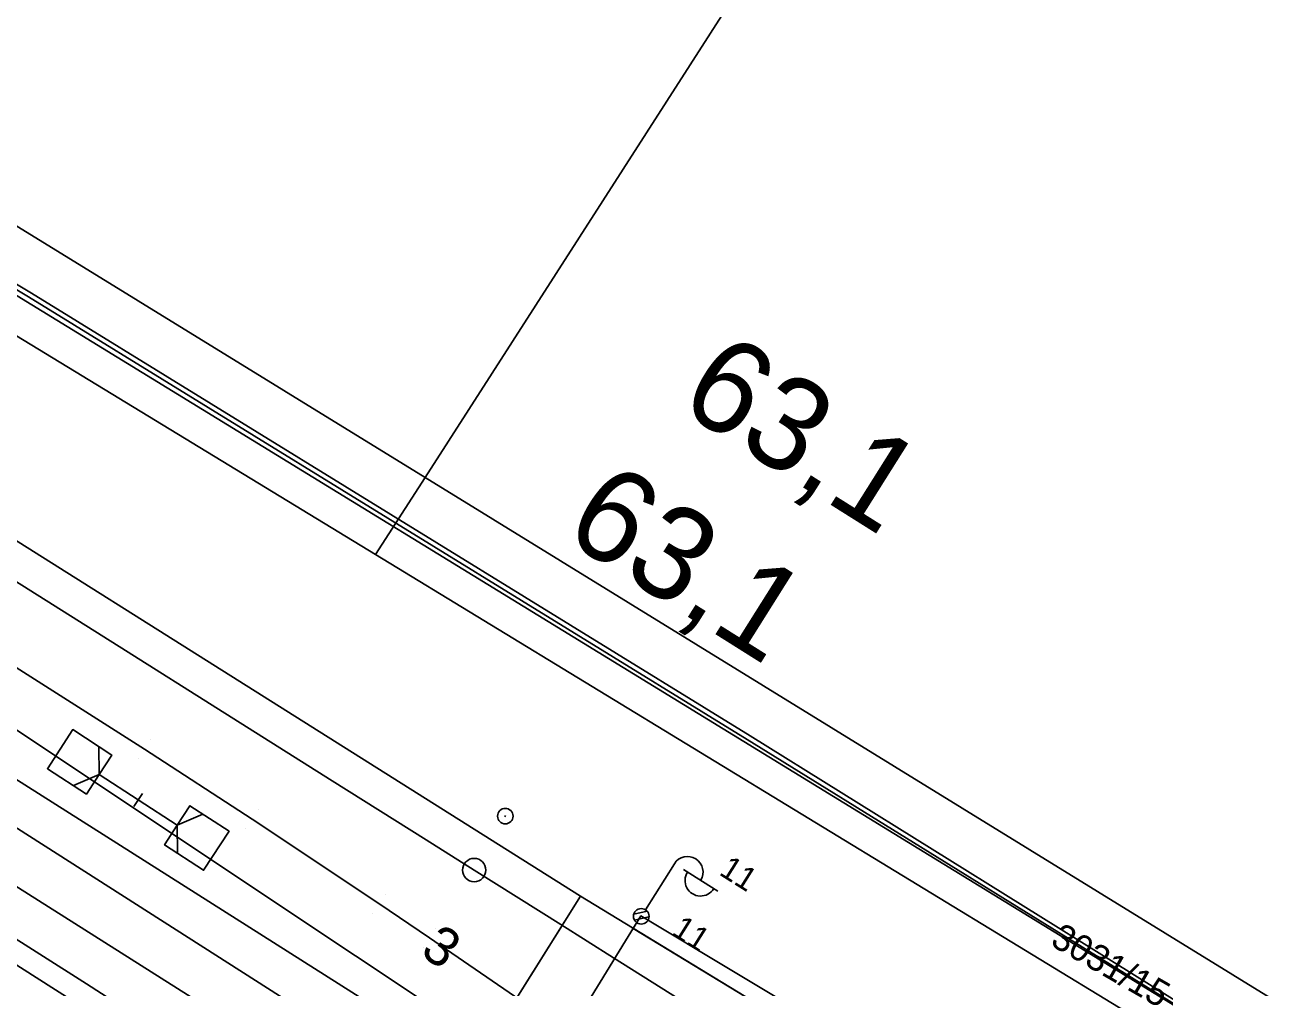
# Model space of a CAD drawing. Extents: x -621168 to -620292, y -1122748 to -1122069.
# Drawn here: x -620574.7 to -620493.7, y -1122527.1 to -1122465.1 of the extents above; entities that cross this region are included whole.
import ezdxf

# ---------------------------------------------------------------- set-up
doc = ezdxf.new("R2010")
doc.units = 0
for name, color, linetype in [('060601_EOV', 7, 'Continuous'), ('060604_ROZVODY_SEE', 7, 'Continuous'), ('CETIN', 7, 'Continuous'), ('HranDP', 7, 'Continuous'), ('Hranice parcel', 7, 'Continuous'), ('Parcelní čísla', 7, 'Continuous'), ('PS 06-14-01_trasa_sdělovací_nové', 7, 'Continuous'), ('SEE', 7, 'Continuous'), ('SSZT', 7, 'Continuous'), ('SSZT-DK', 7, 'Continuous'), ('UZEMNĚNÍ', 7, 'Continuous'), ('Vnitřní kresba', 7, 'Continuous'), ('Vrstva 1', 7, 'Continuous'), ('Vrstva 25', 7, 'Continuous'), ('Vrstva 62', 7, 'Continuous'), ('Vrstva 7', 7, 'Continuous'), ('ČD-T', 7, 'Continuous')]:
    doc.layers.add(name, color=color, linetype=linetype)

msp = doc.modelspace()

# ---------------------------------------------------------------- linework, layer by layer
at = {"layer": '060601_EOV'}
msp.add_lwpolyline([(-620377.179, -1122637.257), (-620411.557, -1122614.916), (-620424.156, -1122607.087), (-620443.525, -1122595.005), (-620456.111, -1122587.123), (-620447.823, -1122572.959), (-620450.948, -1122571.455), (-620470.592, -1122561.479), (-620499.61, -1122545.574), (-620522.038, -1122531.471), (-620538.89, -1122521.208), (-620599.215, -1122483.216), (-620683.524, -1122429.444), (-620729.121, -1122400.659), (-620738.886, -1122415.694), (-620750.529, -1122408.246), (-620763.558, -1122399.82), (-620784.65, -1122386.386), (-620822.218, -1122362.419), (-620817.53, -1122355.085), (-620826.407, -1122348.082), (-620839.916, -1122337.943), (-620848.842, -1122331.997), (-620848.834, -1122331.986)], dxfattribs=at)
at = {"layer": '060604_ROZVODY_SEE'}
msp.add_line((-620535.001, -1122522.477), (-620535.489, -1122523.279), dxfattribs=at)
msp.add_lwpolyline([(-620443.525, -1122595.005), (-620456.111, -1122587.123), (-620447.823, -1122572.959), (-620450.948, -1122571.455), (-620470.592, -1122561.479), (-620499.61, -1122545.574), (-620522.038, -1122531.471), (-620538.89, -1122521.208), (-620599.215, -1122483.216), (-620683.524, -1122429.444), (-620729.121, -1122400.659), (-620738.886, -1122415.694), (-620750.529, -1122408.246), (-620763.558, -1122399.82), (-620784.65, -1122386.386), (-620822.218, -1122362.419), (-620817.53, -1122355.085), (-620826.407, -1122348.082), (-620839.916, -1122337.943), (-620854.567, -1122328.184), (-620868.06, -1122319.694), (-620885.37, -1122308.815), (-620912.868, -1122291.527), (-620913.325, -1122292.255)], dxfattribs=at)
at = {"layer": 'CETIN'}
msp.add_lwpolyline([(-621086.886, -1122186.715), (-621044.703, -1122204.841), (-620975.938, -1122239.692), (-620943.103, -1122258.616), (-620748.436, -1122376.269), (-620484.52, -1122538.147)], dxfattribs=at)
at = {"layer": 'HranDP'}
msp.add_line((-620445.8, -1122563.95), (-620552.09, -1122499.2), dxfattribs=at)
for points in [[(-620847.72, -1122320.67), (-620838.83, -1122326.12), (-620768.63, -1122369.09), (-620748.53, -1122378.52), (-620702.13, -1122406.7), (-620691.02, -1122413.66), (-620638.48, -1122446.57), (-620552.09, -1122499.2)], [(-620821.12, -1122358.76), (-620741.46, -1122408.09), (-620679.51, -1122447.56), (-620545.92, -1122532.26), (-620521.41, -1122548.27), (-620511.29, -1122557.64)]]:
    msp.add_lwpolyline(points, dxfattribs=at)
at = {"layer": 'Hranice parcel'}
for p, q in [((-620548.9, -1122494.24), (-620477.85, -1122383.559)), ((-620688.16, -1122408.5), (-620548.9, -1122494.24)), ((-620552.09, -1122499.2), (-620548.9, -1122494.24)), ((-620548.9, -1122494.24), (-620475.79, -1122539.24)), ((-620445.8, -1122563.95), (-620552.09, -1122499.2))]:
    msp.add_line(p, q, dxfattribs=at)
for points in [[(-620847.72, -1122320.67), (-620838.83, -1122326.12), (-620768.63, -1122369.09), (-620748.53, -1122378.52), (-620702.13, -1122406.7), (-620691.02, -1122413.66), (-620638.48, -1122446.57), (-620552.09, -1122499.2)], [(-620821.12, -1122358.76), (-620741.46, -1122408.09), (-620679.51, -1122447.56), (-620545.92, -1122532.26), (-620521.41, -1122548.27), (-620511.29, -1122557.64)], [(-620821.12, -1122358.76), (-620807.67, -1122367.84), (-620645.72, -1122471.03), (-620587.17, -1122509.18), (-620511.29, -1122557.64)], [(-620557.45, -1122536.96), (-620684.91, -1122455.63), (-620825.92, -1122365.89)]]:
    msp.add_lwpolyline(points, dxfattribs=at)
at = {"layer": 'PS 06-14-01_trasa_sdělovací_nové'}
for points in [[(-620538.89, -1122521.208), (-620538.89, -1122521.208), (-620599.215, -1122483.216), (-620683.524, -1122429.444), (-620756.33, -1122383.523), (-620761.979, -1122392.397), (-620753.366, -1122398.538), (-620735.257, -1122410.106), (-620735.257, -1122410.106)], [(-620377.179, -1122637.257), (-620411.557, -1122614.916), (-620456.111, -1122587.123), (-620544.953, -1122530.859), (-620538.89, -1122521.208), (-620538.89, -1122521.208)]]:
    msp.add_lwpolyline(points, dxfattribs=at)
at = {"layer": 'SEE'}
msp.add_lwpolyline([(-620377.188, -1122637.273), (-620390.254, -1122629.02), (-620411.934, -1122614.961), (-620423.125, -1122608.012), (-620468.337, -1122579.91), (-620468.337, -1122579.91), (-620460.94, -1122568.103), (-620517.418, -1122533.032), (-620535.001, -1122522.477), (-620545.407, -1122539.454), (-620611.375, -1122497.696), (-620665.569, -1122462.755), (-620686.035, -1122449.829), (-620727.537, -1122423.183), (-620794.508, -1122379.862), (-620815.52, -1122356.954), (-620832.168, -1122344.663), (-620847.808, -1122332.592), (-620908.257, -1122294.686)], dxfattribs=at)
at = {"layer": 'SSZT'}
msp.add_lwpolyline([(-620879.238, -1122313.316), (-620842.993, -1122336.61), (-620835.049, -1122343.251), (-620812.66, -1122358.949), (-620764.902, -1122389.752), (-620688.594, -1122438.969), (-620596.981, -1122496.725), (-620576.744, -1122509.484), (-620506.746, -1122556.123), (-620447.293, -1122593.619), (-620377.761, -1122638.259)], dxfattribs=at)
at = {"layer": 'SSZT-DK'}
msp.add_lwpolyline([(-621084.334, -1122182.327), (-621080.248, -1122184.036), (-621051.504, -1122198.928), (-620999.37, -1122227.003), (-620959.935, -1122250.539), (-620931.349, -1122267.519), (-620900.269, -1122286.467), (-620889.147, -1122293.455), (-620783.743, -1122358.818), (-620712.751, -1122398.176), (-620653.117, -1122435.232), (-620617.363, -1122456.738), (-620574.425, -1122482.604), (-620528.157, -1122511.106), (-620496.311, -1122530.834), (-620515.025, -1122558.813), (-620500.383, -1122568.606), (-620465.393, -1122591.454), (-620452.16, -1122605.021), (-620438.234, -1122615.496), (-620392.309, -1122655.212), (-620389.253, -1122658.022)], dxfattribs=at)
at = {"layer": 'UZEMNĚNÍ'}
msp.add_lwpolyline([(-620535.001, -1122522.477), (-620535.489, -1122523.279), (-620522.038, -1122531.471), (-620499.61, -1122545.574), (-620487.514, -1122552.204), (-620470.592, -1122561.479), (-620459.297, -1122567.215), (-620458.667, -1122565.975)], dxfattribs=at)
at = {"layer": 'Vnitřní kresba'}
for p, q in [((-620570.69, -1122526.84), (-620613.12, -1122500)), ((-620504.94, -1122569.2), (-620570.69, -1122526.84))]:
    msp.add_line(p, q, dxfattribs=at)
at = {"layer": 'Vrstva 1'}
msp.add_line((-620544.953, -1122530.859), (-620538.89, -1122521.208), dxfattribs=at)
for points in [[(-620538.89, -1122521.208), (-620599.215, -1122483.216), (-620683.524, -1122429.444), (-620747.38, -1122389.133), (-620756.33, -1122383.523)], [(-620575.439, -1122500.82), (-620568.605, -1122505.122), (-620561.797, -1122509.415), (-620554.878, -1122513.77), (-620548.817, -1122517.58), (-620545.736, -1122519.521), (-620540.158, -1122523.031), (-620536.763, -1122525.164), (-620530.044, -1122529.401), (-620522.74, -1122533.999), (-620516.175, -1122538.134), (-620510.877, -1122541.462), (-620509.772, -1122542.153), (-620508.122, -1122543.191), (-620500.939, -1122547.694), (-620490.94, -1122553.975)], [(-620575.439, -1122500.82), (-620568.605, -1122505.122), (-620561.797, -1122509.415), (-620554.878, -1122513.77), (-620548.817, -1122517.58), (-620545.736, -1122519.521), (-620540.158, -1122523.031), (-620536.763, -1122525.164), (-620530.044, -1122529.401), (-620522.74, -1122533.999), (-620516.175, -1122538.134), (-620510.877, -1122541.462), (-620509.772, -1122542.153), (-620508.122, -1122543.191), (-620500.939, -1122547.694), (-620490.94, -1122553.975)], [(-620582.331, -1122501.971), (-620566.971, -1122511.728), (-620560.029, -1122516.238), (-620551.869, -1122521.685), (-620548.619, -1122523.887), (-620542.396, -1122528.151), (-620538.064, -1122531.158), (-620531.122, -1122535.952), (-620524.966, -1122540.177), (-620518.618, -1122544.427), (-620513.645, -1122547.697), (-620506.55, -1122552.247), (-620496.304, -1122558.659), (-620480.231, -1122568.734), (-620462.233, -1122580.043), (-620447.551, -1122589.267), (-620431.6, -1122599.485), (-620414.27, -1122610.379), (-620398.172, -1122620.479), (-620378.269, -1122633.015), (-620375.666, -1122634.655)]]:
    msp.add_lwpolyline(points, dxfattribs=at)
at = {"layer": 'Vrstva 25'}
for p, q in [((-620534.711, -1122522.078), (-620532.844, -1122519.118)), ((-620534.711, -1122522.078), (-620532.844, -1122519.118)), ((-620532.252, -1122519.491), (-620530.053, -1122520.878)), ((-620532.252, -1122519.491), (-620530.053, -1122520.878)), ((-620535.46, -1122522.37), (-620534.602, -1122522.175)), ((-620535.46, -1122522.37), (-620534.602, -1122522.175)), ((-620535.413, -1122522.743), (-620534.479, -1122522.532)), ((-620535.413, -1122522.743), (-620534.479, -1122522.532))]:
    msp.add_line(p, q, dxfattribs=at)
msp.add_circle((-620534.978, -1122522.501), 0.5, dxfattribs=at)
msp.add_circle((-620534.978, -1122522.501), 0.5, dxfattribs=at)
for centre, start, end in [((-620531.999, -1122519.651), 327.76448, 147.76448), ((-620531.999, -1122519.651), 327.76448, 147.76448), ((-620531.159, -1122520.195), 147.0619, 328.46705), ((-620531.159, -1122520.195), 147.0619, 328.46705)]:
    msp.add_arc(centre, 1, start, end, dxfattribs=at)
at = {"layer": 'Vrstva 62'}
for p, q in [((-620566.596, -1122511.103), (-620566.596, -1122511.103)), ((-620567.346, -1122512.352), (-620567.346, -1122512.352)), ((-620559.628, -1122515.637), (-620559.628, -1122515.637)), ((-620560.43, -1122516.839), (-620560.43, -1122516.839)), ((-620551.476, -1122521.073), (-620551.476, -1122521.073)), ((-620552.263, -1122522.298), (-620552.263, -1122522.298)), ((-620548.218, -1122523.275), (-620548.218, -1122523.275)), ((-620549.02, -1122524.499), (-620549.02, -1122524.499))]:
    msp.add_line(p, q, dxfattribs=at)
at = {"layer": 'Vrstva 7'}
for p, q in [((-620569.888, -1122513.372), (-620567.372, -1122515.006)), ((-620567.644, -1122515.425), (-620567.1, -1122514.587)), ((-620567.1, -1122514.587), (-620567.644, -1122515.425)), ((-620564.856, -1122516.64), (-620567.372, -1122515.006)), ((-620543.775, -1122516.023), (-620543.691, -1122516.077)), ((-620543.775, -1122516.023), (-620543.691, -1122516.077))]:
    msp.add_line(p, q, dxfattribs=at)
for points in [[(-620569.888, -1122513.372), (-620569.071, -1122512.114), (-620571.586, -1122510.479), (-620573.221, -1122512.995), (-620570.705, -1122514.629), (-620569.888, -1122513.372)], [(-620571.545, -1122514.084), (-620569.888, -1122513.372), (-620569.911, -1122511.568)], [(-620564.856, -1122516.64), (-620565.673, -1122517.898), (-620563.158, -1122519.533), (-620561.523, -1122517.017), (-620564.039, -1122515.383), (-620564.856, -1122516.64)], [(-620563.199, -1122515.928), (-620564.856, -1122516.64), (-620564.833, -1122518.444)]]:
    msp.add_lwpolyline(points, dxfattribs=at)
for centre, radius in [((-620543.733, -1122516.05), 0.5), ((-620543.733, -1122516.05), 0.5), ((-620545.736, -1122519.521), 0.75), ((-620545.736, -1122519.521), 0.75)]:
    msp.add_circle(centre, radius, dxfattribs=at)
at = {"layer": 'ČD-T'}
msp.add_lwpolyline([(-621084.188, -1122182.075), (-621080.06, -1122183.802), (-621051.317, -1122198.693), (-620999.183, -1122226.768), (-620959.747, -1122250.305), (-620931.162, -1122267.284), (-620900.082, -1122286.233), (-620888.96, -1122293.22), (-620783.556, -1122358.583), (-620712.564, -1122397.941), (-620652.93, -1122434.998), (-620617.176, -1122456.504), (-620574.237, -1122482.37), (-620527.969, -1122510.872), (-620481.077, -1122540.08), (-620497.003, -1122565.384), (-620499.265, -1122568.979), (-620465.206, -1122591.22), (-620451.973, -1122604.786), (-620438.046, -1122615.261), (-620392.122, -1122654.977), (-620389.098, -1122657.757)], dxfattribs=at)

# ---------------------------------------------------------------- texts
at = {"layer": 'Parcelní čísla'}
msp.add_text('3031/15', height=1.7, rotation=330, dxfattribs=at).set_placement((-620508.708, -1122524.327))
at = {"layer": 'Vrstva 1'}
msp.add_text('3', height=2.5, rotation=325.58106, dxfattribs=at).set_placement((-620549.289, -1122524.943))
at = {"layer": 'Vrstva 25'}
for p in [(-620530.034, -1122519.779), (-620533.092, -1122523.631)]:
    msp.add_text('11', height=1.5, rotation=327.76448, dxfattribs=at).set_placement(p)
at = {"layer": 'Vrstva 7'}
for p in [(-620532.736, -1122489.737), (-620540.158, -1122498.069)]:
    msp.add_text('63,1', height=6, rotation=327.81952, dxfattribs=at).set_placement(p)

doc.saveas('drawing.dxf')
